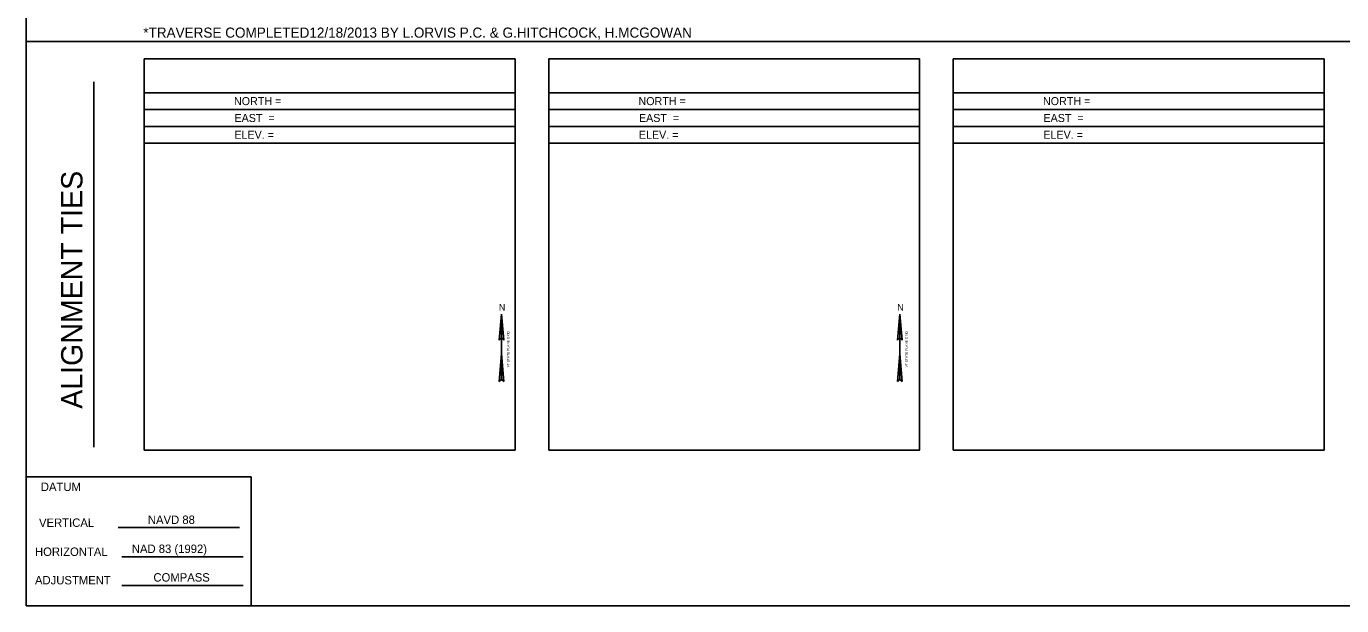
# Model space of a CAD drawing. Extents: x 1504239 to 1504879, y 438007 to 438427.
# Drawn here: x 1504239.3 to 1504629.5, y 438006.7 to 438178.5 of the extents above; entities that cross this region are included whole.
import ezdxf

# ---------------------------------------------------------------- set-up
doc = ezdxf.new("R2010")
doc.units = 0
for name, color, linetype in [('Default', 7, 'Continuous'), ('NBL1', 7, 'Continuous'), ('NBL2', 7, 'Continuous'), ('NNA_P', 7, 'Continuous')]:
    doc.layers.add(name, color=color, linetype=linetype)

msp = doc.modelspace()

# ---------------------------------------------------------------- linework, layer by layer
at = {"layer": 'NBL1'}
msp.add_lwpolyline([(1504239.27, 438006.69), (1504879.27, 438006.69), (1504879.27, 438426.69), (1504239.27, 438426.69)], close=True, dxfattribs=at)
at = {"layer": 'NBL2'}
for p, q in [((1504239.27, 438174.03), (1504879.27, 438174.03)), ((1504259.27, 438053.69), (1504259.27, 438162.03)), ((1504384.27, 438158.86), (1504274.27, 438158.86)), ((1504504.27, 438158.86), (1504394.27, 438158.86)), ((1504624.27, 438158.86), (1504514.27, 438158.86)), ((1504384.27, 438153.86), (1504274.27, 438153.86)), ((1504504.27, 438153.86), (1504394.27, 438153.86)), ((1504624.27, 438153.86), (1504514.27, 438153.86)), ((1504384.27, 438148.86), (1504274.27, 438148.86)), ((1504504.27, 438148.86), (1504394.27, 438148.86)), ((1504624.27, 438148.86), (1504514.27, 438148.86)), ((1504384.27, 438143.86), (1504274.27, 438143.86)), ((1504504.27, 438143.86), (1504394.27, 438143.86)), ((1504624.27, 438143.86), (1504514.27, 438143.86)), ((1504305.94, 438044.95), (1504239.27, 438044.95)), ((1504305.94, 438044.95), (1504305.94, 438006.69)), ((1504305.94, 438044.95), (1504305.94, 438006.69)), ((1504266.51, 438029.92), (1504302.51, 438029.89)), ((1504267.62, 438021.15), (1504303.62, 438021.15)), ((1504267.62, 438012.71), (1504303.62, 438012.68))]:
    msp.add_line(p, q, dxfattribs=at)
for points in [[(1504274.27, 438052.86), (1504384.27, 438052.86), (1504384.27, 438168.86), (1504274.27, 438168.86)], [(1504394.27, 438052.86), (1504504.27, 438052.86), (1504504.27, 438168.86), (1504394.27, 438168.86)], [(1504514.27, 438052.86), (1504624.27, 438052.86), (1504624.27, 438168.86), (1504514.27, 438168.86)]]:
    msp.add_lwpolyline(points, close=True, dxfattribs=at)
at = {"layer": 'NNA_P'}
for p, q in [((1504379.54, 438085.41), (1504380.23, 438093.2)), ((1504380.23, 438073.82), (1504380.23, 438093.2)), ((1504380.92, 438085.41), (1504380.23, 438093.2)), ((1504497.72, 438085.41), (1504498.41, 438093.2)), ((1504498.42, 438073.82), (1504498.41, 438093.2)), ((1504499.11, 438085.41), (1504498.41, 438093.2)), ((1504379.54, 438085.41), (1504380.23, 438086.17)), ((1504380.93, 438085.41), (1504380.23, 438086.17)), ((1504497.72, 438085.41), (1504498.41, 438086.17)), ((1504499.11, 438085.41), (1504498.42, 438086.17)), ((1504380.23, 438081.35), (1504379.51, 438073.18)), ((1504380.23, 438081.35), (1504380.95, 438073.18)), ((1504498.42, 438081.35), (1504497.7, 438073.18)), ((1504498.42, 438081.35), (1504499.14, 438073.18)), ((1504380.23, 438073.82), (1504379.51, 438073.18)), ((1504380.23, 438073.82), (1504380.95, 438073.18)), ((1504498.42, 438073.82), (1504497.7, 438073.18)), ((1504498.42, 438073.82), (1504499.14, 438073.18))]:
    msp.add_line(p, q, dxfattribs=at)

# ---------------------------------------------------------------- texts
at = {"layer": 'Default'}
msp.add_text('*TRAVERSE COMPLETED12/18/2013 BY L.ORVIS P.C. & G.HITCHCOCK, H.MCGOWAN', height=3, dxfattribs=at).set_placement((1504273.98, 438175.17))
at = {"layer": 'NBL2'}
for s, height, p in [('NORTH =             ', 2.375, (1504300.89, 438155.17)), ('NORTH =             ', 2.375, (1504420.89, 438155.17)), ('NORTH =             ', 2.375, (1504540.89, 438155.17)), ('EAST  =             ', 2.375, (1504301.03, 438150.17)), ('EAST  =             ', 2.375, (1504421.03, 438150.17)), ('EAST  =             ', 2.375, (1504541.03, 438150.17)), ('ELEV. =             ', 2.375, (1504301, 438145.17)), ('ELEV. =             ', 2.375, (1504421, 438145.17)), ('ELEV. =             ', 2.375, (1504541, 438145.17)), ('DATUM', 2.5, (1504243.59, 438040.71)), ('  NAVD 88 ', 2.5, (1504273.49, 438030.93)), ('HORIZONTAL', 2.5, (1504241.85, 438021.45)), ('NAD 83 (1992)  ', 2.5, (1504270.58, 438022.32)), ('   COMPASS', 2.5, (1504274.2, 438013.84)), ('ADJUSTMENT', 2.5, (1504241.85, 438013.01))]:
    msp.add_text(s, height=height, dxfattribs=at).set_placement(p)
for s, height, rotation, p in [('ALIGNMENT TIES', 6.3332, 90, (1504255.94, 438065.1)), ('VERTICAL', 2.5, 0.1439, (1504243.05, 438030.04))]:
    msp.add_text(s, height=height, rotation=rotation, dxfattribs=at).set_placement(p)
at = {"layer": 'NNA_P'}
for p in [(1504379.47, 438094.21), (1504497.65, 438094.21)]:
    msp.add_text('N', height=1.97, dxfattribs=at).set_placement(p)
for p in [(1504382.58, 438077.39), (1504500.77, 438077.39)]:
    msp.add_text('VT STATE PLANE GRID', height=0.7, rotation=90.0204, dxfattribs=at).set_placement(p)

doc.saveas('drawing.dxf')
